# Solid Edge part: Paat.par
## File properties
Author: Marvin
Template: Iso Metric Part.par
Last saved by: Marvin
Revision: 2
Application: Solid Edge
Accuracy: 0.990
Username: Marvin
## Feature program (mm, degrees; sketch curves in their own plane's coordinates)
sketch for "unnamed Protrusion 1" plane through (0, 0, 0) normal (0, 0, 1) x-axis (1, 0, 0)
  line (-1205, -1468.8686) -> (-1102.1397, -293.1698)
  arc centre (1079.2608, -484.0176) radius 2189.7331 from (-328.2725, 1193.4153) to (-1102.1397, -293.1698) ccw
  line (0, 1468.8686) -> (-328.2725, 1193.4153)
  line (0, -1468.8686) -> (0, 1468.8686)
  line (-1205, -1468.8686) -> (0, -1468.8686)
extrude "unnamed Protrusion 1" add finite 70 along -normal
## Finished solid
Body 1: solid body, 7 faces, 15 edges, 10 vertices.
  Faces by surface: plane 6, cylinder 1
  Edges by curve: line 13, circle 2
Bounding box of the edges (mm): 1205.000 x 2937.737 x 70.000, from (-1205, -1468.8686, -70) to (0, 1468.8686, 0).
Cylindrical faces by radius (mm): R2189.7331 x1
Planar faces by outward normal: +x 1, +z 1, -y 1, -z 1, oblique 2
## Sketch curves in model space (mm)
line (0, -1468.8686, 0) -> (0, 1468.8686, 0)
line (0, 1468.8686, 0) -> (-328.2725, 1193.4153, 0)
arc centre (1079.2608, -484.0176, 0) radius 2189.7331 from (-328.2725, 1193.4153, 0) through (-863.0562, 527.0886, 0) to (-1102.1397, -293.1698, 0)
line (-1205, -1468.8686, 0) -> (-1102.1397, -293.1698, 0)
line (-1205, -1468.8686, 0) -> (0, -1468.8686, 0)
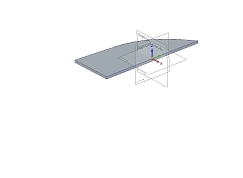
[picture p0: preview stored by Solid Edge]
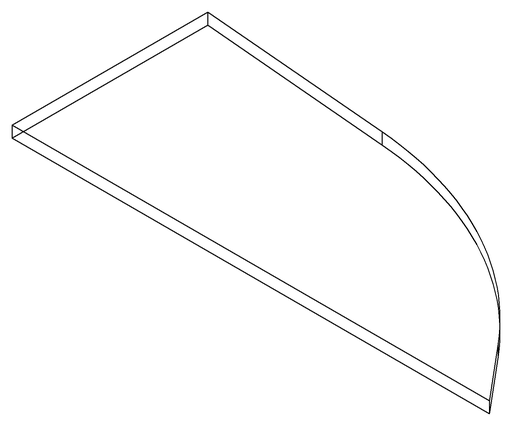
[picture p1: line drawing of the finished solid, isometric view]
